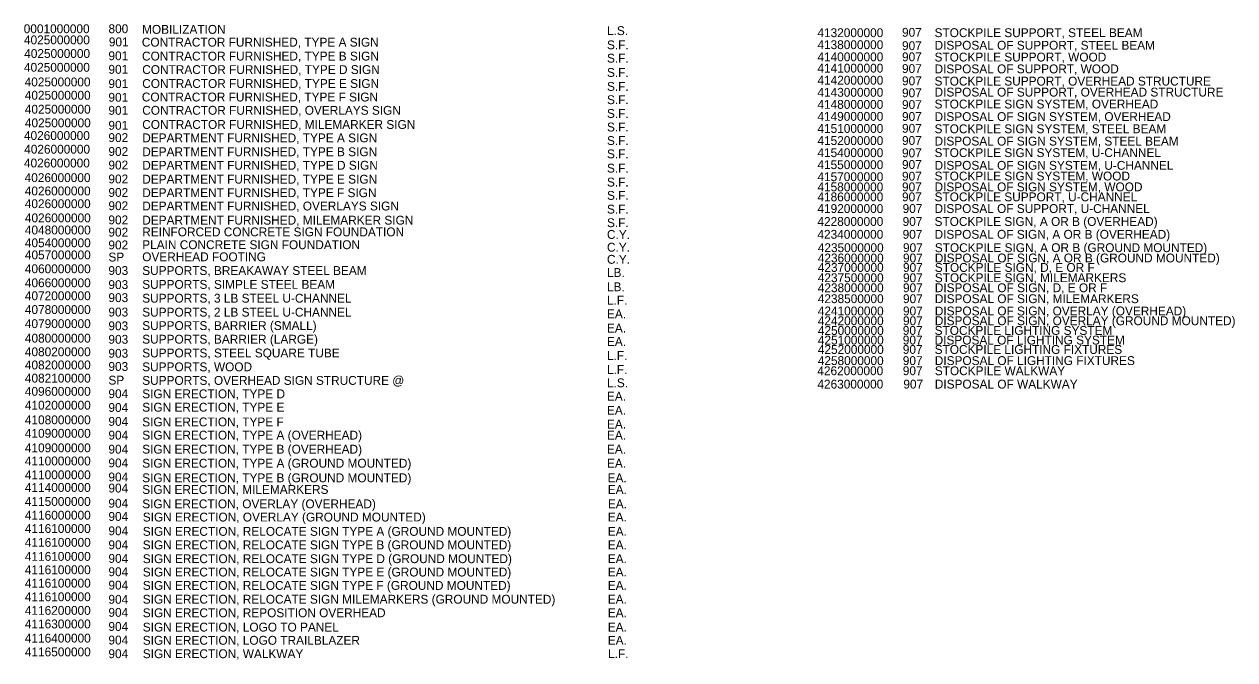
# Model space of a CAD drawing. Extents: x -2362 to 1945, y 0 to 1100.
# Drawn here: x -2362 to -1455, y 298 to 774 of the extents above; entities that cross this region are included whole.
import ezdxf

# ---------------------------------------------------------------- set-up
doc = ezdxf.new("R2010")
doc.units = 0
doc.layers.add('Default', color=7, linetype='Continuous')

msp = doc.modelspace()

# ---------------------------------------------------------------- texts
at = {"layer": 'Default'}
for s, height, p in [('0001000000', 6.638, (-2362.24, 767.68)), ('800', 6.638, (-2298.72, 767.68)), ('MOBILIZATION', 6.6381, (-2273.54, 767.22)), ('L.S.', 6.638, (-1925.09, 766.26)), ('4132000000', 6.638, (-1767.35, 764.72)), ('907', 6.638, (-1703.95, 765)), ('STOCKPILE SUPPORT, STEEL BEAM', 6.6381, (-1679.57, 764.74)), ('4025000000', 6.638, (-2362.07, 759.34)), ('901', 6.638, (-2298.46, 757.81)), ('CONTRACTOR FURNISHED, TYPE A SIGN ', 6.6381, (-2273.73, 757.61)), ('S.F.', 6.638, (-1925.09, 755.61)), ('4138000000', 6.638, (-1767.35, 755.73)), ('4025000000', 6.638, (-2361.89, 749.11)), ('901', 6.638, (-2298.76, 747.41)), ('CONTRACTOR FURNISHED, TYPE B SIGN ', 6.6381, (-2273.58, 747.2)), ('4140000000', 6.638, (-1767.35, 746.63)), ('907', 6.638, (-1703.95, 754.98)), ('907', 6.638, (-1703.95, 746.65)), ('STOCKPILE SUPPORT, WOOD', 6.6381, (-1679.57, 746.46)), ('DISPOSAL OF SUPPORT, STEEL BEAM', 6.6381, (-1679.57, 755.29)), ('4025000000', 6.638, (-2362.07, 738.77)), ('S.F.', 6.638, (-1925.09, 745.64)), ('4141000000', 6.638, (-1767.35, 738.15)), ('907', 6.638, (-1703.95, 737.81)), ('DISPOSAL OF SUPPORT, WOOD', 6.6381, (-1679.57, 737.58)), ('901', 6.638, (-2298.76, 737.26)), ('CONTRACTOR FURNISHED, TYPE D SIGN', 6.6381, (-2273.43, 737.06)), ('S.F.', 6.638, (-1925.09, 734.92)), ('4142000000', 6.638, (-1767.35, 729.09)), ('907', 6.638, (-1703.95, 728.61)), ('STOCKPILE SUPPORT, OVERHEAD STRUCTURE', 6.6381, (-1679.57, 728.42)), ('4025000000', 6.638, (-2361.56, 727.8)), ('901', 6.638, (-2298.76, 726.54)), ('CONTRACTOR FURNISHED, TYPE E SIGN', 6.6381, (-2273.43, 726.62)), ('S.F.', 6.638, (-1925.09, 724.46)), ('4143000000', 6.638, (-1767.35, 720.03)), ('907', 6.638, (-1703.95, 719.68)), ('DISPOSAL OF SUPPORT, OVERHEAD STRUCTURE', 6.6381, (-1679.57, 720.19)), ('4025000000', 6.638, (-2361.47, 717.82)), ('901', 6.638, (-2298.76, 716.29)), ('CONTRACTOR FURNISHED, TYPE F SIGN', 6.6381, (-2273.73, 716.5)), ('S.F.', 6.638, (-1925.09, 714.49)), ('4148000000', 6.638, (-1767.35, 710.97)), ('907', 6.638, (-1703.95, 710.82)), ('STOCKPILE SIGN SYSTEM, OVERHEAD', 6.6381, (-1679.57, 711.24)), ('4025000000', 6.638, (-2361.45, 707.36)), ('901', 6.638, (-2298.77, 706.51)), ('CONTRACTOR FURNISHED, OVERLAYS SIGN', 6.6381, (-2273.43, 706.53)), ('S.F.', 6.638, (-1925.09, 704.18)), ('4149000000', 6.638, (-1767.35, 701.99)), ('907', 6.638, (-1703.95, 701.89)), ('DISPOSAL OF SIGN SYSTEM, OVERHEAD', 6.6381, (-1679.57, 701.81)), ('4025000000', 6.638, (-2361.39, 697.13)), ('901', 6.638, (-2298.77, 695.3)), ('CONTRACTOR FURNISHED, MILEMARKER SIGN', 6.6381, (-2273.43, 695.91)), ('S.F.', 6.638, (-1925.09, 694.01)), ('4151000000', 6.638, (-1767.35, 692.92)), ('907', 6.638, (-1703.95, 693.02)), ('STOCKPILE SIGN SYSTEM, STEEL BEAM', 6.6381, (-1679.57, 692.69)), ('4026000000', 6.638, (-2362.07, 687.6)), ('902', 6.638, (-2298.77, 686.07)), ('DEPARTMENT FURNISHED, TYPE A SIGN ', 6.6381, (-2273.43, 685.87)), ('S.F.', 6.638, (-1925.09, 683.87)), ('4152000000', 6.638, (-1767.35, 683.84)), ('907', 6.638, (-1703.95, 683.92)), ('DISPOSAL OF SIGN SYSTEM, STEEL BEAM', 6.6381, (-1679.57, 683.46)), ('4026000000', 6.638, (-2361.89, 677.37)), ('902', 6.638, (-2298.77, 675.66)), ('DEPARTMENT FURNISHED, TYPE B SIGN ', 6.6381, (-2273.43, 675.46)), ('S.F.', 6.638, (-1925.09, 673.9)), ('4154000000', 6.638, (-1767.35, 674.78)), ('907', 6.638, (-1703.95, 674.62)), ('STOCKPILE SIGN SYSTEM, U-CHANNEL', 6.6381, (-1679.57, 674.8)), ('4026000000', 6.638, (-2362.07, 667.03)), ('902', 6.638, (-2298.77, 665.52)), ('DEPARTMENT FURNISHED, TYPE D SIGN', 6.6381, (-2273.43, 665.32)), ('4155000000', 6.638, (-1767.35, 665.77)), ('907', 6.638, (-1703.95, 665.91)), ('DISPOSAL OF SIGN SYSTEM, U-CHANNEL', 6.6381, (-1679.57, 665.28)), ('4026000000', 6.638, (-2361.56, 656.06)), ('S.F.', 6.638, (-1925.09, 663.18)), ('4157000000', 6.638, (-1767.35, 656.76)), ('907', 6.638, (-1703.95, 657.1)), ('STOCKPILE SIGN SYSTEM, WOOD', 6.6381, (-1679.57, 657.27)), ('902', 6.638, (-2298.77, 655.08)), ('DEPARTMENT FURNISHED, TYPE E SIGN', 6.6381, (-2273.43, 654.88)), ('S.F.', 6.638, (-1925.09, 652.72)), ('4158000000', 6.638, (-1767.35, 649.14)), ('907', 6.638, (-1703.95, 649.14)), ('DISPOSAL OF SIGN SYSTEM, WOOD', 6.6381, (-1679.57, 649.14)), ('4026000000', 6.638, (-2361.47, 646.08)), ('902', 6.638, (-2298.77, 644.96)), ('DEPARTMENT FURNISHED, TYPE F SIGN', 6.6381, (-2273.43, 644.76)), ('S.F.', 6.638, (-1925.09, 642.75)), ('4186000000', 6.638, (-1767.35, 641.65)), ('907', 6.638, (-1703.95, 641.65)), ('STOCKPILE SUPPORT, U-CHANNEL', 6.6381, (-1679.57, 641.65)), ('4026000000', 6.638, (-2361.45, 636.51)), ('902', 6.638, (-2298.77, 635)), ('DEPARTMENT FURNISHED, OVERLAYS SIGN', 6.6381, (-2273.43, 634.79)), ('S.F.', 6.638, (-1925.09, 632.44)), ('4192000000', 6.638, (-1767.35, 632.88)), ('907', 6.638, (-1703.5, 632.88)), ('DISPOSAL OF SUPPORT, U-CHANNEL', 6.6381, (-1679.57, 632.88)), ('4026000000', 6.638, (-2361.39, 625.89)), ('902', 6.638, (-2298.77, 624.38)), ('DEPARTMENT FURNISHED, MILEMARKER SIGN', 6.6381, (-2273.43, 624.17)), ('S.F.', 6.638, (-1925.09, 622.27)), ('4228000000', 6.638, (-1767.35, 623.19)), ('907', 6.638, (-1703.5, 623.19)), ('STOCKPILE SIGN, A OR B (OVERHEAD)', 6.6381, (-1679.57, 623.19)), ('4048000000', 6.638, (-2361.39, 616.81)), ('902', 6.638, (-2298.77, 615.21)), ('REINFORCED CONCRETE SIGN FOUNDATION', 6.6381, (-2273.43, 615.38)), ('C.Y.', 6.638, (-1925.09, 613.47)), ('4234000000', 6.638, (-1767.35, 613.56)), ('907', 6.638, (-1703.5, 613.56)), ('DISPOSAL OF SIGN, A OR B (OVERHEAD)', 6.6381, (-1679.57, 613.56)), ('4054000000', 6.638, (-2361.39, 607.21)), ('902', 6.638, (-2298.77, 605.61)), ('PLAIN CONCRETE SIGN FOUNDATION', 6.6381, (-2273.43, 605.78)), ('C.Y.', 6.638, (-1925.09, 603.88)), ('4235000000', 6.638, (-1767.08, 603.55)), ('907', 6.638, (-1703.22, 603.55)), ('STOCKPILE SIGN, A OR B (GROUND MOUNTED)', 6.6381, (-1679.38, 603.55)), ('4057000000', 6.638, (-2361.39, 598.14)), ('SP', 6.638, (-2298.77, 596.53)), ('OVERHEAD FOOTING', 6.6381, (-2273.43, 596.71)), ('C.Y.', 6.638, (-1925.09, 594.8)), ('4236000000', 6.638, (-1767.08, 595.82)), ('907', 6.638, (-1703.22, 595.82)), ('DISPOSAL OF SIGN, A OR B (GROUND MOUNTED)', 6.6381, (-1679.38, 595.82)), ('4060000000', 6.638, (-2361.39, 587.74)), ('903', 6.638, (-2298.77, 586.42)), ('SUPPORTS, BREAKAWAY STEEL BEAM', 6.6381, (-2273.43, 586.4)), ('LB.', 6.638, (-1925.09, 584.94)), ('4237000000', 6.638, (-1767.08, 588.72)), ('907', 6.638, (-1703.22, 588.72)), ('STOCKPILE SIGN, D, E OR F', 6.6381, (-1679.38, 588.72)), ('4066000000', 6.638, (-2361.39, 577.23)), ('903', 6.638, (-2298.77, 575.86)), ('SUPPORTS, SIMPLE STEEL BEAM', 6.6381, (-2273.43, 576.03)), ('LB.', 6.638, (-1925.09, 574.22)), ('4237500000', 6.638, (-1767.08, 581.02)), ('907', 6.638, (-1703.22, 581.02)), ('STOCKPILE SIGN, MILEMARKERS', 6.6381, (-1679.38, 581.02)), ('4072000000', 6.638, (-2361.39, 567.51)), ('903', 6.638, (-2298.77, 566.09)), ('SUPPORTS, 3 LB STEEL U-CHANNEL', 6.6381, (-2273.43, 565.67)), ('4238000000', 6.638, (-1767.08, 573.51)), ('4238500000', 6.638, (-1767.08, 565.3)), ('907', 6.638, (-1703.22, 573.51)), ('907', 6.638, (-1703.22, 565.3)), ('DISPOSAL OF SIGN, D, E OR F', 6.6381, (-1679.38, 573.51)), ('DISPOSAL OF SIGN, MILEMARKERS', 6.6381, (-1679.38, 565.3)), ('4078000000', 6.638, (-2361.39, 557.14)), ('L.F.', 6.638, (-1925.09, 564.2)), ('4241000000', 6.638, (-1767.08, 556.1)), ('907', 6.638, (-1703.22, 556.1)), ('DISPOSAL OF SIGN, OVERLAY (OVERHEAD)', 6.6381, (-1679.38, 556.1)), ('903', 6.638, (-2298.77, 555.28)), ('SUPPORTS, 2 LB STEEL U-CHANNEL', 6.6381, (-2273.43, 555.2)), ('EA.', 6.638, (-1925.09, 553.96)), ('4242000000', 6.638, (-1767.08, 548.77)), ('907', 6.638, (-1703.22, 548.77)), ('DISPOSAL OF SIGN, OVERLAY (GROUND MOUNTED)', 6.6381, (-1679.38, 548.77)), ('4079000000', 6.638, (-2361.39, 546.59)), ('903', 6.638, (-2298.77, 544.96)), ('SUPPORTS, BARRIER (SMALL)', 6.6381, (-2273.43, 545.14)), ('EA.', 6.638, (-1925.09, 543.27)), ('4250000000', 6.638, (-1767.03, 541.49)), ('907', 6.638, (-1703.35, 541.49)), ('STOCKPILE LIGHTING SYSTEM', 6.6381, (-1679.5, 541.49)), ('4080000000', 6.638, (-2361.39, 535.72)), ('903', 6.638, (-2298.77, 534.85)), ('SUPPORTS, BARRIER (LARGE)', 6.6381, (-2273.43, 534.92)), ('EA.', 6.638, (-1925.09, 533.19)), ('4251000000', 6.638, (-1767.03, 534.28)), ('907', 6.638, (-1703.35, 534.28)), ('DISPOSAL OF LIGHTING SYSTEM', 6.6381, (-1679.5, 534.28)), ('4080200000', 6.638, (-2361.39, 525.5)), ('903', 6.638, (-2298.77, 524.37)), ('SUPPORTS, STEEL SQUARE TUBE', 6.6381, (-2273.43, 524.61)), ('L.F.', 6.638, (-1925.09, 522.75)), ('4252000000', 6.638, (-1767.03, 527.24)), ('907', 6.638, (-1703.35, 527.24)), ('STOCKPILE LIGHTING FIXTURES', 6.6381, (-1679.5, 527.24)), ('4082000000', 6.638, (-2361.39, 515.62)), ('903', 6.638, (-2298.77, 514.49)), ('SUPPORTS, WOOD', 6.6381, (-2273.43, 514.22)), ('L.F.', 6.638, (-1925.09, 512.2)), ('4262000000', 6.638, (-1767.41, 511.28)), ('4258000000', 6.638, (-1767.08, 518.89)), ('907', 6.638, (-1703.35, 518.89)), ('907', 6.638, (-1703.35, 511.28)), ('STOCKPILE WALKWAY', 6.6381, (-1679.38, 511.28)), ('DISPOSAL OF LIGHTING FIXTURES', 6.6381, (-1679.38, 518.89)), ('4082100000', 6.638, (-2361.39, 505.75)), ('SP', 6.638, (-2298.77, 504.24)), ('SUPPORTS, OVERHEAD SIGN STRUCTURE @ ', 6.6381, (-2273.43, 504.04)), ('L.S.', 6.638, (-1925.09, 502.25)), ('4096000000', 6.638, (-2361.39, 495.84)), ('904', 6.638, (-2298.77, 494.08)), ('SIGN ERECTION, TYPE D', 6.6381, (-2273.43, 493.98)), ('4263000000', 6.638, (-1767.37, 501.26)), ('907', 6.638, (-1702.93, 501.26)), ('DISPOSAL OF WALKWAY', 6.6381, (-1679.38, 501.26)), ('4102000000', 6.638, (-2361.39, 485.46)), ('904', 6.638, (-2298.77, 483.73)), ('SIGN ERECTION, TYPE E', 6.6381, (-2273.43, 483.94)), ('EA.', 6.638, (-1925.09, 492.18)), ('4108000000', 6.638, (-2361.39, 474.48)), ('EA.', 6.638, (-1925.09, 481.64)), ('904', 6.638, (-2298.77, 473.3)), ('SIGN ERECTION, TYPE F', 6.6381, (-2273.43, 472.91)), ('EA.', 6.638, (-1925.09, 471.28)), ('4109000000', 6.638, (-2361.39, 464.38)), ('904', 6.638, (-2298.77, 463.01)), ('SIGN ERECTION, TYPE A (OVERHEAD)', 6.6381, (-2273.43, 463.02)), ('EA.', 6.638, (-1925.09, 463.02)), ('4109000000', 6.638, (-2361.39, 453.5)), ('904', 6.638, (-2298.77, 452.48)), ('SIGN ERECTION, TYPE B (OVERHEAD)', 6.6381, (-2273.43, 452.47)), ('EA.', 6.638, (-1925.09, 452.47)), ('4110000000', 6.638, (-2361.39, 443.64)), ('904', 6.638, (-2298.77, 442.17)), ('SIGN ERECTION, TYPE A (GROUND MOUNTED)', 6.6381, (-2273.43, 441.94)), ('EA.', 6.638, (-1925.06, 441.94)), ('4110000000', 6.638, (-2361.39, 433.27)), ('904', 6.638, (-2298.77, 431.65)), ('SIGN ERECTION, TYPE B (GROUND MOUNTED)', 6.6381, (-2273.43, 431.01)), ('EA.', 6.638, (-1924.64, 431.01)), ('4114000000', 6.638, (-2361.39, 423.8)), ('904', 6.638, (-2298.77, 423.32)), ('SIGN ERECTION, MILEMARKERS', 6.6381, (-2273.43, 422.28)), ('EA.', 6.638, (-1924.5, 422.28)), ('4115000000', 6.638, (-2361.39, 413.27)), ('904', 6.638, (-2298.77, 411.93)), ('SIGN ERECTION, OVERLAY (OVERHEAD)', 6.6381, (-2273.43, 411.48)), ('EA.', 6.638, (-1924.41, 411.48)), ('4116000000', 6.638, (-2361.39, 403)), ('904', 6.638, (-2298.77, 402.04)), ('SIGN ERECTION, OVERLAY (GROUND MOUNTED)', 6.6381, (-2273.02, 401.59)), ('4116100000', 6.638, (-2361.39, 392.99)), ('EA.', 6.638, (-1924.5, 401.59)), ('904', 6.638, (-2298.76, 391.26)), ('SIGN ERECTION, RELOCATE SIGN TYPE A (GROUND MOUNTED)', 6.6381, (-2273.02, 390.86)), ('EA.', 6.638, (-1924.5, 390.86)), ('4116100000', 6.638, (-2361.39, 382.63)), ('904', 6.638, (-2298.76, 380.79)), ('SIGN ERECTION, RELOCATE SIGN TYPE B (GROUND MOUNTED)', 6.6381, (-2273.02, 380.73)), ('EA.', 6.638, (-1924.5, 380.73)), ('4116100000', 6.638, (-2361.39, 372.11)), ('904', 6.638, (-2298.76, 370.59)), ('SIGN ERECTION, RELOCATE SIGN TYPE D (GROUND MOUNTED)', 6.6381, (-2273.02, 370.38)), ('EA.', 6.638, (-1924.5, 370.38)), ('4116100000', 6.638, (-2361.39, 362.09)), ('904', 6.638, (-2298.76, 360.58)), ('SIGN ERECTION, RELOCATE SIGN TYPE E (GROUND MOUNTED)', 6.6381, (-2273.02, 360.37)), ('EA.', 6.638, (-1924.5, 360.37)), ('4116100000', 6.638, (-2361.39, 352.07)), ('904', 6.638, (-2298.76, 350.56)), ('SIGN ERECTION, RELOCATE SIGN TYPE F (GROUND MOUNTED)', 6.6381, (-2273.02, 350.35)), ('EA.', 6.638, (-1924.5, 350.35)), ('4116100000', 6.638, (-2361.39, 341.83)), ('904', 6.638, (-2298.76, 339.92)), ('SIGN ERECTION, RELOCATE SIGN MILEMARKERS (GROUND MOUNTED)', 6.6381, (-2273.02, 339.98)), ('EA.', 6.638, (-1924.5, 339.98)), ('4116200000', 6.638, (-2361.39, 331.63)), ('904', 6.638, (-2298.76, 330.15)), ('SIGN ERECTION, REPOSITION OVERHEAD ', 6.6381, (-2273.02, 329.84)), ('EA.', 6.638, (-1924.5, 329.84)), ('4116300000', 6.638, (-2361.39, 321.45)), ('4116400000', 6.638, (-2361.39, 310.85)), ('904', 6.638, (-2298.76, 319.54)), ('SIGN ERECTION, LOGO TO PANEL', 6.6381, (-2273.02, 319.1)), ('EA.', 6.638, (-1924.5, 319.1)), ('904', 6.638, (-2298.76, 309.38)), ('SIGN ERECTION, LOGO TRAILBLAZER', 6.6381, (-2273.02, 309.18)), ('EA.', 6.638, (-1924.5, 309.18)), ('4116500000', 6.638, (-2361.39, 300.49)), ('904', 6.638, (-2298.76, 299.13)), ('SIGN ERECTION, WALKWAY', 6.6381, (-2273.02, 299.14)), ('L.F.', 6.638, (-1924.29, 299.14))]:
    msp.add_text(s, height=height, dxfattribs=at).set_placement(p)

doc.saveas('drawing.dxf')
